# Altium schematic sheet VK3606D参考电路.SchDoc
size A4
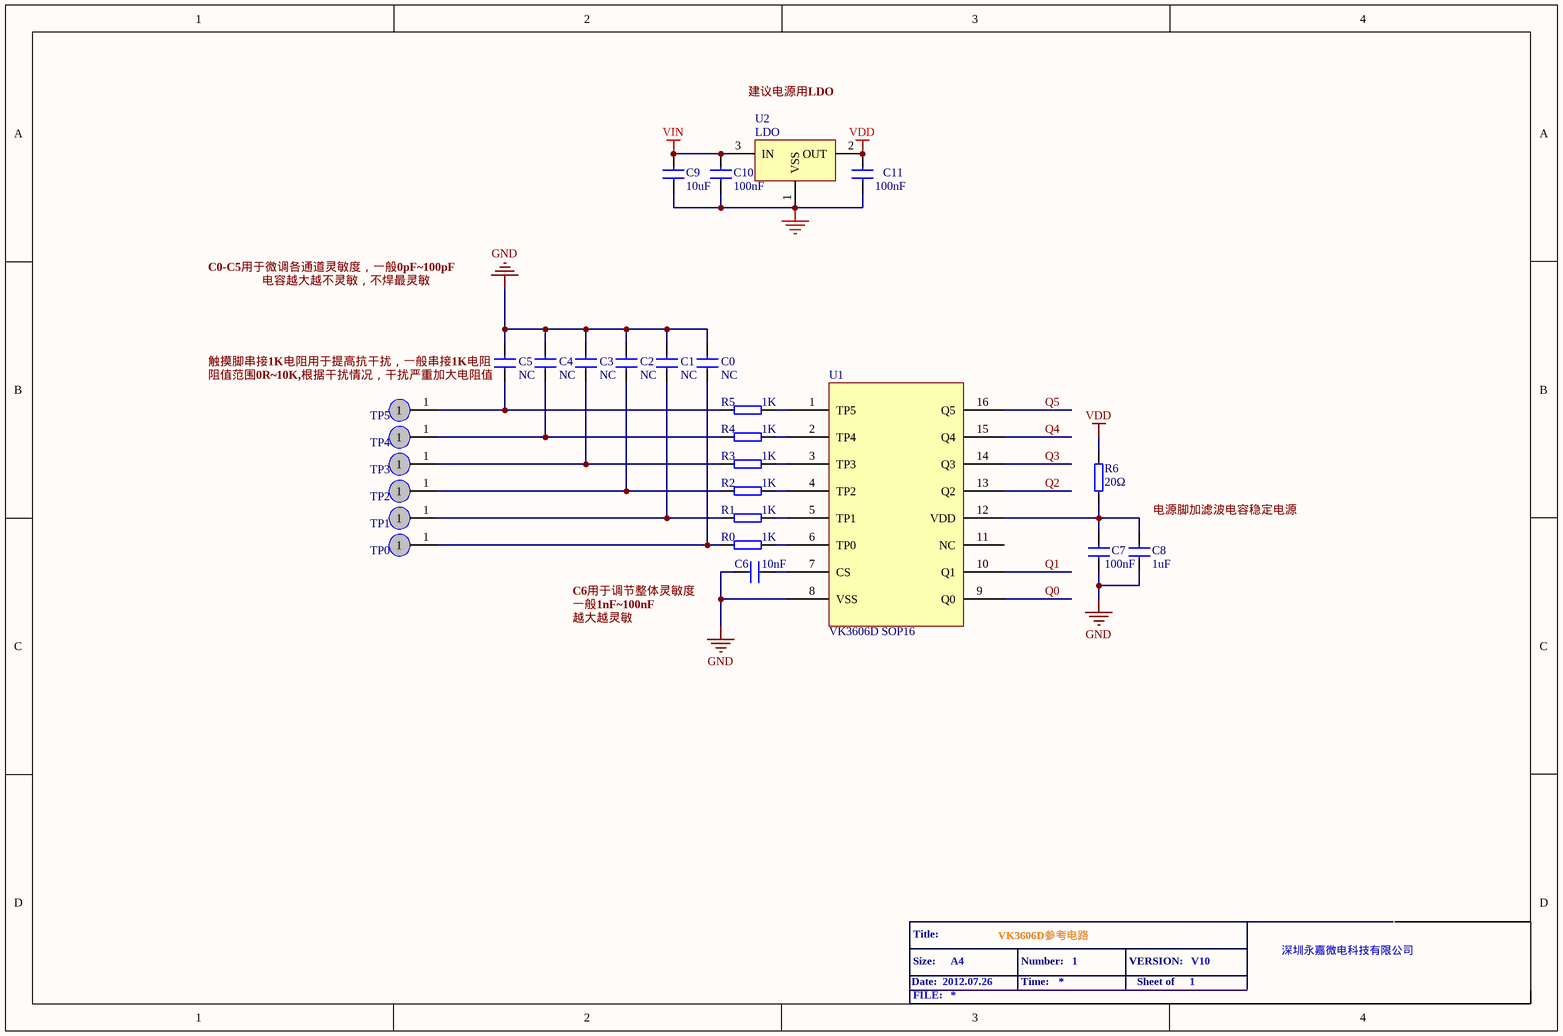
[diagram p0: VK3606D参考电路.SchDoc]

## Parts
C0  value NC  [0603-C]  (hidden comment: 10uF)
C1  value NC  [0603-C]  (hidden comment: 10uF)
C2  value NC  [0603-C]  (hidden comment: 10uF)
C3  value NC  [0603-C]  (hidden comment: 10uF)
C4  value NC  [0603-C]  (hidden comment: 10uF)
C5  value NC  [0603-C]  (hidden comment: 10uF)
C6  value 10nF  [0603-C]  (hidden comment: 10uF)
C7  100nF  [0603-C]
C8  value 1uF  [0603-C]  (hidden comment: 10uF)
C9  10uF  [0805-C]
C10  100nF  [0805-C]
C11  100nF  [0805-C]
R0  1K  [0603-R]
R1  1K  [0603-R]
R2  1K  [0603-R]
R3  1K  [0603-R]
R4  1K  [0603-R]
R5  1K  [0603-R]
R6  20Ω  [0603-R]
TP0  TPAD  [TP-PAD0]  (value not drawn)
TP1  TPAD  [TP-PAD0]  (value not drawn)
TP2  TPAD  [TP-PAD0]  (value not drawn)
TP3  TPAD  [TP-PAD0]  (value not drawn)
TP4  TPAD  [TP-PAD0]  (value not drawn)
TP5  TPAD  [TP-PAD0]  (value not drawn)
U1  VK3606D SOP16
U2  LDO  [SOT-23]

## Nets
GND: C0.2 C1.2 C2.2 C3.2 C4.2 C5.2 C6.2 C7.2 C8.2 C9.2 C10.2 C11.2 U1.8(VSS) U2.1(VSS)
VDD: C11.1 R6.1 U2.2(OUT)
VIN: C9.1 C10.1 U2.3(IN)
Q0: U1.9(Q0)
Q1: U1.10(Q1)
Q2: U1.13(Q2)
Q3: U1.14(Q3)
Q4: U1.15(Q4)
Q5: U1.16(Q5)
NetC0_1: C0.1 R0.2 TP0.1
NetC1_1: C1.1 R1.2 TP1.1
NetC2_1: C2.1 R2.2 TP2.1
NetC3_1: C3.1 R3.2 TP3.1
NetC4_1: C4.1 R4.2 TP4.1
NetC5_1: C5.1 R5.2 TP5.1
NetC6_1: C6.1 U1.7(CS)
NetC7_1: C7.1 C8.1 R6.2 U1.12(VDD)
NetR0_1: R0.1 U1.6(TP0)
NetR1_1: R1.1 U1.5(TP1)
NetR2_1: R2.1 U1.4(TP2)
NetR3_1: R3.1 U1.3(TP3)
NetR4_1: R4.1 U1.2(TP4)
NetR5_1: R5.1 U1.1(TP5)

Not connected (* = marked no-connect by the designer): U1 11(NC)

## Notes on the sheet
- 建议电源用LDO
- C0-C5用于微调各通道灵敏度，一般0pF
  00pF
- 电容越大越不灵敏，不焊最灵敏
- 触摸脚串接1K电阻用于提高抗干扰，一般串接1K电阻
- 阻值范围0R
  0K,根据干扰情况，干扰严重加大电阻值
- (near C8) 电源脚加滤波电容稳定电源
- C6用于调节整体灵敏度
- 一般1nF
  00nF
- 越大越灵敏
- Date:
- Title:
- Size:
- 2012.07.26
- A4
- VK3606D参考电路
- Number:
- Time:
- 1
- VERSION:
- Sheet of
- V10
- 深圳永嘉微电科技有限公司
- FILE:

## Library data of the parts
C0-C11 = CAP: Capacitor
R0-R6 = RES: Resistor
TP0-TP5 = TPAD: TESTING
U2 = V6206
